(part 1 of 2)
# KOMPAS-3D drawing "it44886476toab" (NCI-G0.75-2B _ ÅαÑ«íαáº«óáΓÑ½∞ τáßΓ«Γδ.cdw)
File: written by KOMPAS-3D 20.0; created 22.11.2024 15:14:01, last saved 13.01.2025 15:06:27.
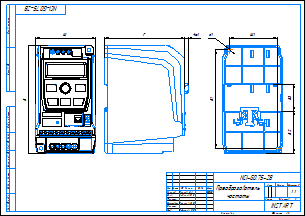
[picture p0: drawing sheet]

Sheet 1: A3, landscape

Document properties: Автор: admin; Полное имя файла: C:\Уралов Работа\Уралов (локальная)\ПЧ\! Китай 3Д-модель NCI\NCI 0.75-2.2 4B\NCI 0.75-2.2 4B.m3d

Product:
- Part/product: it44886476toab
    Масса: 2.32322
  - Body: Тело 17
      Масса: 0.0117014
  - Body: Тело 374
      Масса: 5.48304e-05
  - Body: Тело 265
      Масса: 1.32696e-05
  - Body: Тело 266
      Масса: 1.7366e-05
  - Body: Тело 267
      Масса: 1.7366e-05
  - Body: Тело 103
      Масса: 1.32696e-05
  - Body: Тело 573
      Масса: 4.06595e-05
  - Body: Тело 348
      Масса: 1.32696e-05
  - Body: Тело 270
      Масса: 1.7366e-05
  - Body: Тело 77
      Масса: 1.32696e-05
  - Body: Тело 244
      Масса: 1.65581e-05
  - Body: Тело 536
      Масса: 0.000158536
  - Body: Тело 377
      Масса: 1.65581e-05
  - Body: Тело 272
      Масса: 1.7366e-05
  - Body: Тело 273
      Масса: 5.48304e-05
  - Body: Тело 238
      Масса: 1.7366e-05
  - Body: Тело 274
      Масса: 1.7366e-05
  - Body: Тело 277
      Масса: 1.7366e-05
  - Body: Тело 530
      Масса: 5.61948e-05
  - Body: Тело 278
      Масса: 1.7366e-05
  - Body: Тело 282
      Масса: 1.7366e-05
  - Body: Тело 477
      Масса: 1.51773e-05
  - Body: Тело 526
      Масса: 5.61948e-05
  - Body: Тело 391
      Масса: 1.32696e-05
  - Body: Тело 285
      Масса: 5.48304e-05
  - Body: Тело 287
      Масса: 1.32696e-05
  - Body: Тело 290
      Масса: 0.000413213
  - Body: Тело 269
      Масса: 5.48304e-05
  - Body: Тело 292
      Масса: 1.7366e-05
  - Body: Тело 33
      Масса: 0.00516019
  - Body: Тело 252
      Масса: 5.48304e-05
  - Body: Тело 294
      Масса: 0.000413213
  - Body: Тело 297
      Масса: 3.64631e-05
  - Body: Тело 299
      Масса: 3.64028e-05
  - Body: Тело 283
      Масса: 1.7366e-05
  - Body: Тело 300
      Масса: 1.65581e-05
  - Body: Тело 303
      Масса: 1.65581e-05
  - Body: Тело 516
      Масса: 0.00507377
  - Body: Тело 384
      Масса: 5.48304e-05
  - Body: Тело 360
      Масса: 1.32696e-05
  - Body: Тело 347
      Масса: 1.32696e-05
  - Body: Тело 304
      Масса: 1.65581e-05
  - Body: Тело 307
      Масса: 0.000213463
  - Body: Тело 308
      Масса: 0.000413213
  - Body: Тело 180
      Масса: 1.32696e-05
  - Body: Тело 240
      Масса: 1.7366e-05
  - Body: Тело 309
      Масса: 1.32696e-05
  - Body: Тело 473
      Масса: 0.00425494
  - Body: Тело 311
      Масса: 5.48304e-05
  - Body: Тело 122
      Масса: 1.65581e-05
  - Body: Тело 560
      Масса: 1.65581e-05
  - Body: Тело 312
      Масса: 5.48304e-05
  - Body: Тело 317
      Масса: 1.32696e-05
  - Body: Тело 318
      Масса: 1.32696e-05
  - Body: Тело 321
      Масса: 1.32696e-05
  - Body: Тело 324
      Масса: 1.32696e-05
  - Body: Тело 480
      Масса: 1.51773e-05
  - Body: Тело 288
      Масса: 1.7366e-05
  - Body: Тело 293
      Масса: 5.48304e-05
  - Body: Тело 325
      Масса: 1.32696e-05
  - Body: Тело 99
      Масса: 1.65581e-05
  - Body: Тело 617
      Масса: 1.63919e-05
  - Body: Тело 327
      Масса: 1.32696e-05
  - Body: Тело 31
      Масса: 0.0078835
  - Body: Тело 100
      Масса: 1.65581e-05
  - Body: Тело 105
      Масса: 1.32696e-05
  - Body: Тело 328
      Масса: 1.7366e-05
  - Body: Тело 301
      Масса: 1.65581e-05
  - Body: Тело 331
      Масса: 1.7366e-05
  - Body: Тело 332
      Масса: 1.7366e-05
  - Body: Тело 446
      Масса: 0.000307437
  - Body: Тело 337
      Масса: 1.7366e-05
  - Body: Тело 338
      Масса: 1.7366e-05
  - Body: Тело 570
      Масса: 4.06595e-05
  - Body: Тело 340
      Масса: 1.32696e-05
  - Body: Тело 196
      Масса: 1.32696e-05
  - Body: Тело 357
      Масса: 1.65581e-05
  - Body: Тело 346
      Масса: 1.32696e-05
  - Body: Тело 335
      Масса: 1.32696e-05
  - Body: Тело 281
      Масса: 1.32696e-05
  - Body: Тело 362
      Масса: 1.32696e-05
  - Body: Тело 353
      Масса: 1.7366e-05
  - Body: Тело 355
      Масса: 5.48304e-05
  - Body: Тело 466
      Масса: 0.00829114
  - Body: Тело 358
      Масса: 5.48304e-05
  - Body: Тело 359
      Масса: 1.7366e-05
  - Body: Тело 286
      Масса: 1.7366e-05
  - Body: Тело 86
      Масса: 1.32696e-05
  - Body: Тело 310
      Масса: 1.7366e-05
  - Body: Тело 368
      Масса: 1.32696e-05
  - Body: Тело 370
      Масса: 1.32696e-05
  - Body: Тело 333
      Масса: 1.32696e-05
  - Body: Тело 628
      Масса: 1.51773e-05
  - Body: Тело 371
      Масса: 1.7366e-05
  - Body: Тело 75
      Масса: 1.32696e-05
  - Body: Тело 373
      Масса: 1.32696e-05
  - Body: Тело 375
      Масса: 1.32696e-05
  - Body: Тело 351
      Масса: 2.90876e-05
  - Body: Тело 76
      Масса: 1.65581e-05
  - Body: Тело 259
      Масса: 1.7366e-05
  - Body: Тело 378
      Масса: 0.000413213
  - Body: Тело 95
      Масса: 0.000935996
  - Body: Тело 372
      Масса: 1.7366e-05
  - Body: Тело 322
      Масса: 1.32696e-05
  - Body: Тело 380
      Масса: 1.32696e-05
  - Body: Тело 639
      Масса: 1.63919e-05
  - Body: Тело 385
      Масса: 1.32696e-05
  - Body: Тело 291
      Масса: 0.000213463
  - Body: Тело 386
      Масса: 1.32696e-05
  - Body: Тело 229
      Масса: 1.32696e-05
  - Body: Тело 388
      Масса: 1.32696e-05
  - Body: Тело 389
      Масса: 1.65581e-05
  - Body: Тело 93
      Масса: 3.83377e-05
  - Body: Тело 390
      Масса: 1.65581e-05
  - Body: Тело 143
      Масса: 1.32696e-05
  - Body: Тело 394
      Масса: 1.32696e-05
  - Body: Тело 395
      Масса: 1.32696e-05
  - Body: Тело 354
      Масса: 0.000213463
  - Body: Тело 396
      Масса: 1.7366e-05
  - Body: Тело 397
      Масса: 1.32696e-05
  - Body: Тело 398
      Масса: 1.65581e-05
  - Body: Тело 479
      Масса: 1.51773e-05
  - Body: Тело 402
      Масса: 1.7366e-05
  - Body: Тело 59
      Масса: 1.32696e-05
  - Body: Тело 339
      Масса: 1.32696e-05
  - Body: Тело 404
      Масса: 1.32696e-05
  - Body: Тело 89
      Масса: 0.00142218
  - Body: Тело 406
      Масса: 1.65581e-05
  - Body: Тело 393
      Масса: 1.32696e-05
  - Body: Тело 52
      Масса: 1.32696e-05
  - Body: Тело 407
      Масса: 5.48304e-05
  - Body: Тело 97
      Масса: 0.0015961
  - Body: Тело 410
      Масса: 5.48304e-05
  - Body: Тело 636
      Масса: 1.65581e-05
  - Body: Тело 412
      Масса: 1.7366e-05
  - Body: Тело 413
      Масса: 1.32696e-05
  - Body: Тело 414
      Масса: 1.32696e-05
  - Body: Тело 537
      Масса: 0.000158536
  - Body: Тело 415
      Масса: 1.7366e-05
  - Body: Тело 235
      Масса: 1.7366e-05
  - Body: Тело 419
      Масса: 1.32696e-05
  - Body: Тело 648
      Масса: 0.00426189
  - Body: Тело 420
      Масса: 1.7366e-05
  - Body: Тело 186
      Масса: 1.32696e-05
  - Body: Тело 422
      Масса: 5.48304e-05
  - Body: Тело 381
      Масса: 1.7366e-05
  - Body: Тело 423
      Масса: 1.32696e-05
  - Body: Тело 424
      Масса: 1.7366e-05
  - Body: Тело 98
      Масса: 1.65581e-05
  - Body: Тело 305
      Масса: 1.65581e-05
  - Body: Тело 425
      Масса: 1.32696e-05
  - Body: Тело 365
      Масса: 1.32696e-05
  - Body: Тело 271
      Масса: 1.32696e-05
  - Body: Тело 206
      Масса: 1.32696e-05
  - Body: Тело 429
      Масса: 0.146258
  - Body: Тело 334
      Масса: 1.7366e-05
  - Body: Тело 430
      Масса: 0.146258
  - Body: Тело 350
      Масса: 1.7366e-05
  - Body: Тело 345
      Масса: 1.32696e-05
  - Body: Тело 431
      Масса: 0.146258
  - Body: Тело 364
      Масса: 1.32696e-05
  - Body: Тело 329
      Масса: 1.32696e-05
  - Body: Тело 434
      Масса: 0.000355433
  - Body: Тело 5
      Масса: 0.000355433
  - Body: Тело 124
      Масса: 1.65581e-05
  - Body: Тело 344
      Масса: 1.32696e-05
  - Body: Тело 436
      Масса: 0.000355433
  - Body: Тело 439
      Масса: 0.00113358
  - Body: Тело 606
      Масса: 0.000137594
  - Body: Тело 323
      Масса: 1.32696e-05
  - Body: Тело 441
      Масса: 0.00113358
  - Body: Тело 442
      Масса: 0.000355433
  - Body: Тело 554
      Масса: 4.06595e-05
  - Body: Тело 444
      Масса: 0.000355433
  - Body: Тело 246
      Масса: 1.65581e-05
  - Body: Тело 445
      Масса: 0.00113358
  - Body: Тело 438
      Масса: 0.000355433
  - Body: Тело 106
      Масса: 1.32696e-05
  - Body: Тело 508
      Масса: 1.51773e-05
  - Body: Тело 577
      Масса: 1.7366e-05
  - Body: Тело 392
      Масса: 1.32696e-05
  - Body: Тело 193
      Масса: 1.32696e-05
  - Body: Тело 448
      Масса: 0.000307437
  - Body: Тело 481
      Масса: 1.51773e-05
  - Body: Тело 450
      Масса: 6.34685e-05
  - Body: Тело 222
      Масса: 1.32696e-05
  - Body: Тело 315
      Масса: 1.7366e-05
  - Body: Тело 452
      Масса: 1.63919e-05
  - Body: Тело 53
      Масса: 1.32696e-05
  - Body: Тело 401
      Масса: 1.32696e-05
  - Body: Тело 418
      Масса: 1.7366e-05
  - Body: Тело 517
      Масса: 0.00106884
  - Body: Тело 417
      Масса: 1.32696e-05
  - Body: Тело 453
      Масса: 1.63919e-05
  - Body: Тело 454
      Масса: 0.000382752
  - Body: Тело 428
      Масса: 0.146258
  - Body: Тело 455
      Масса: 1.51773e-05
  - Body: Тело 539
      Масса: 1.51773e-05
  - Body: Тело 457
      Масса: 1.51773e-05
  - Body: Тело 459
      Масса: 3.90329e-05
  - Body: Тело 557
      Масса: 0.00166679
  - Body: Тело 569
      Масса: 1.32696e-05
  - Body: Тело 578
      Масса: 1.32696e-05
  - Body: Тело 626
      Масса: 1.32696e-05
  - Body: Тело 134
      Масса: 1.32696e-05
  - Body: Тело 582
      Масса: 1.65581e-05
  - Body: Тело 203
      Масса: 1.32696e-05
  - Body: Тело 572
      Масса: 1.32696e-05
  - Body: Тело 567
      Масса: 1.32696e-05
  - Body: Тело 207
      Масса: 1.32696e-05
  - Body: Тело 645
      Масса: 1.32696e-05
  - Body: Тело 559
      Масса: 1.65581e-05
  - Body: Тело 152
      Масса: 1.32696e-05
  - Body: Тело 449
      Масса: 0.0658364
  - Body: Тело 316
      Масса: 1.32696e-05
  - Body: Тело 376
      Масса: 1.32696e-05
  - Body: Тело 575
      Масса: 1.32696e-05
  - Body: Тело 576
      Масса: 1.32696e-05
  - Body: Тело 85
      Масса: 1.32696e-05
  - Body: Тело 574
      Масса: 4.06595e-05
  - Body: Тело 399
      Масса: 1.32696e-05
  - Body: Тело 320
      Масса: 1.32696e-05
  - Body: Тело 275
      Масса: 1.7366e-05
  - Body: Тело 213
      Масса: 1.32696e-05
  - Body: Тело 625
      Масса: 1.32696e-05
  - Body: Тело 644
      Масса: 0.000158536
  - Body: Тело 584
      Масса: 4.06595e-05
  - Body: Тело 70
      Масса: 1.65581e-05
  - Body: Тело 588
      Масса: 1.32696e-05
  - Body: Тело 276
      Масса: 1.7366e-05
  - Body: Тело 363
      Масса: 1.32696e-05
  - Body: Тело 474
      Масса: 1.51773e-05
  - Body: Тело 548
      Масса: 2.98222e-05
  - Body: Тело 409
      Масса: 5.48304e-05
  - Body: Тело 472
      Масса: 0.00329327
  - Body: Тело 533
      Масса: 5.61948e-05
  - Body: Тело 647
      Масса: 0.00426189
  - Body: Тело 586
      Масса: 1.32696e-05
  - Body: Тело 262
      Масса: 1.7366e-05
  - Body: Тело 562
      Масса: 0.000382752
  - Body: Тело 379
      Масса: 1.32696e-05
  - Body: Тело 632
      Масса: 1.51773e-05
  - Body: Тело 565
      Масса: 4.06595e-05
  - Body: Тело 118
      Масса: 0.000413213
  - Body: Тело 597
      Масса: 7.12116e-06
  - Body: Тело 613
      Масса: 1.63919e-05
  - Body: Тело 387
      Масса: 1.32696e-05
  - Body: Тело 593
      Масса: 1.32696e-05
  - Body: Тело 408
      Масса: 5.48304e-05
  - Body: Тело 109
      Масса: 1.32696e-05
  - Body: Тело 163
      Масса: 1.32696e-05
  - Body: Тело 488
      Масса: 1.51773e-05
  - Body: Тело 367
      Масса: 1.32696e-05
  - Body: Тело 411
      Масса: 5.48304e-05
  - Body: Тело 583
      Масса: 4.06595e-05
  - Body: Тело 598
      Масса: 7.12116e-06
  - Body: Тело 551
      Масса: 0.000255388
  - Body: Тело 405
      Масса: 1.32696e-05
  - Body: Тело 619
      Масса: 1.32696e-05
  - Body: Тело 361
      Масса: 1.32696e-05
  - Body: Тело 589
      Масса: 1.32696e-05
  - Body: Тело 499
      Масса: 1.51773e-05
  - Body: Тело 440
      Масса: 0.000355433
  - Body: Тело 640
      Масса: 1.63919e-05
  - Body: Тело 150
      Масса: 1.32696e-05
  - Body: Тело 568
      Масса: 1.32696e-05
  - Body: Тело 194
      Масса: 1.32696e-05
  - Body: Тело 251
      Масса: 1.7366e-05
  - Body: Тело 342
      Масса: 0.00166679
  - Body: Тело 604
      Масса: 5.61948e-05
  - Body: Тело 650
      Масса: 0.00426189
  - Body: Тело 161
      Масса: 1.32696e-05
  - Body: Тело 611
      Масса: 0.000158536
  - Body: Тело 210
      Масса: 1.32696e-05
  - Body: Тело 540
      Масса: 1.51773e-05
  - Body: Тело 296
      Масса: 3.6965e-05
  - Body: Тело 601
      Масса: 5.61948e-05
  - Body: Тело 484
      Масса: 0.000158536
  - Body: Тело 622
      Масса: 1.32696e-05
  - Body: Тело 527
      Масса: 0.000141095
  - Body: Тело 624
      Масса: 1.32696e-05
  - Body: Тело 121
      Масса: 0.000413213
  - Body: Тело 600
      Масса: 5.61948e-05
  - Body: Тело 603
      Масса: 5.61948e-05
  - Body: Тело 607
      Масса: 1.32696e-05
  - Body: Тело 289
      Масса: 1.7366e-05
  - Body: Тело 471
      Масса: 0.00329327
  - Body: Тело 313
      Масса: 1.7366e-05
  - Body: Тело 591
      Масса: 7.12116e-06
  - Body: Тело 356
      Масса: 1.65581e-05
  - Body: Тело 306
      Масса: 1.65581e-05
  - Body: Тело 541
      Масса: 0.000158536
  - Body: Тело 511
      Масса: 1.51773e-05
  - Body: Тело 160
      Масса: 1.32696e-05
  - Body: Тело 566
      Масса: 1.32696e-05
  - Body: Тело 563
      Масса: 4.06595e-05
  - Body: Тело 638
      Масса: 1.7366e-05
  - Body: Тело 489
      Масса: 1.51773e-05
  - Body: Тело 456
      Масса: 1.51773e-05
  - Body: Тело 485
      Масса: 0.000158536
  - Body: Тело 284
      Масса: 1.7366e-05
  - Body: Тело 138
      Масса: 2.23009e-05
  - Body: Тело 225
      Масса: 1.32696e-05
  - Body: Тело 546
      Масса: 0.000255388
  - Body: Тело 113
      Масса: 0.000413213
  - Body: Тело 642
      Масса: 3.90329e-05
  - Body: Тело 618
      Масса: 1.63919e-05
  - Body: Тело 525
      Масса: 0.000213463
  - Body: Тело 164
      Масса: 1.32696e-05
  - Body: Тело 253
      Масса: 1.7366e-05
  - Body: Тело 561
      Масса: 1.65581e-05
  - Body: Тело 594
      Масса: 1.32696e-05
  - Body: Тело 482
      Масса: 1.51773e-05
  - Body: Тело 81
      Масса: 1.32696e-05
  - Body: Тело 280
      Масса: 1.32696e-05
  - Body: Тело 494
      Масса: 1.51773e-05
  - Body: Тело 641
      Масса: 3.90329e-05
  - Body: Тело 564
      Масса: 4.06595e-05
  - Body: Тело 633
      Масса: 1.51773e-05
  - Body: Тело 518
      Масса: 0.00166679
  - Body: Тело 620
      Масса: 1.7366e-05
  - Body: Тело 497
      Масса: 1.51773e-05
  - Body: Тело 151
      Масса: 1.65581e-05
  - Body: Тело 302
      Масса: 1.65581e-05
  - Body: Тело 110
      Масса: 1.32696e-05
  - Body: Тело 646
      Масса: 0.000137594
  - Body: Тело 264
      Масса: 1.7366e-05
  - Body: Тело 635
      Масса: 1.65581e-05
  - Body: Тело 608
      Масса: 0.00166679
  - Body: Тело 460
      Масса: 3.90329e-05
  - Body: Тело 403
      Масса: 1.7366e-05
  - Body: Тело 612
      Масса: 0.000158536
  - Body: Тело 492
      Масса: 1.51773e-05
  - Body: Тело 139
      Масса: 0.000194606
  - Body: Тело 400
      Масса: 1.7366e-05
  - Body: Тело 605
      Масса: 5.61948e-05
  - Body: Тело 623
      Масса: 1.32696e-05
  - Body: Тело 117
      Масса: 0.000413213
  - Body: Тело 185
      Масса: 1.32696e-05
  - Body: Тело 631
      Масса: 1.51773e-05
  - Body: Тело 580
      Масса: 1.32696e-05
  - Body: Тело 349
      Масса: 1.7366e-05
  - Body: Тело 621
      Масса: 1.32696e-05
  - Body: Тело 627
      Масса: 0.000255388
  - Body: Тело 531
      Масса: 5.61948e-05
  - Body: Тело 649
      Масса: 0.00426189
  - Body: Тело 585
      Масса: 4.06595e-05
  - Body: Тело 236
      Масса: 1.7366e-05
  - Body: Тело 513
      Масса: 1.51773e-05
  - Body: Тело 426
      Масса: 1.32696e-05
  - Body: Тело 341
      Масса: 0.00166679
  - Body: Тело 470
      Масса: 0.00329329
  - Body: Тело 382
      Масса: 5.48304e-05
  - Body: Тело 227
      Масса: 1.32696e-05
  - Body: Тело 476
      Масса: 1.51773e-05
  - Body: Тело 538
      Масса: 1.51773e-05
  - Body: Тело 596
      Масса: 1.32696e-05
  - Body: Тело 609
      Масса: 1.7366e-05
  - Body: Тело 610
      Масса: 0.00166679
  - Body: Тело 263
      Масса: 1.7366e-05
  - Body: Тело 629
      Масса: 1.51773e-05
  - Body: Тело 336
      Масса: 3.64028e-05
  - Body: Тело 495
      Масса: 1.51773e-05
  - Body: Тело 168
      Масса: 1.32696e-05
  - Body: Тело 298
      Масса: 3.64495e-05
  - Body: Тело 279
      Масса: 1.32696e-05
  - Body: Тело 72
      Масса: 1.65581e-05
  - Body: Тело 500
      Масса: 1.51773e-05
  - Body: Тело 505
      Масса: 1.51773e-05
  - Body: Тело 558
      Масса: 0.00726683
  - Body: Тело 630
      Масса: 1.51773e-05
  - Body: Тело 602
      Масса: 5.61948e-05
  - Body: Тело 556
      Масса: 0.00166679
  - Body: Тело 555
      Масса: 0.00166679
  - Body: Тело 634
      Масса: 1.51773e-05
  - Body: Тело 435
      Масса: 0.00113358
  - Body: Тело 416
      Масса: 1.7366e-05
  - Body: Тело 190
      Масса: 1.32696e-05
  - Body: Тело 330
      Масса: 1.7366e-05
  - Body: Тело 28
      Масса: 0.00135688
  - Body: Тело 553
      Масса: 4.06595e-05
  - Body: Тело 176
      Масса: 1.32696e-05
  - Body: Тело 552
      Масса: 4.06595e-05
  - Body: Тело 534
      Масса: 1.32696e-05
  - Body: Тело 595
      Масса: 1.32696e-05
  - Body: Тело 23
      Масса: 0.0243258
  - Body: Тело 247
      Масса: 1.7366e-05
  - Body: Тело 314
      Масса: 1.7366e-05
  - Body: Тело 126
      Масса: 0.000512664
  - Body: Тело 157
      Масса: 1.32696e-05
  - Body: Тело 550
      Масса: 0.000255388
  - Body: Тело 32
      Масса: 0.0135217
  - Body: Тело 592
      Масса: 7.12116e-06
  - Body: Тело 366
      Масса: 1.7366e-05
  - Body: Тело 504
      Масса: 1.51773e-05
  - Body: Тело 258
      Масса: 1.7366e-05
  - Body: Тело 421
      Масса: 1.7366e-05
  - Body: Тело 35
      Масса: 0.262997
  - Body: Тело 204
      Масса: 1.32696e-05
  - Body: Тело 549
      Масса: 0.000255388
  - Body: Тело 257
      Масса: 1.7366e-05
  - Body: Тело 614
      Масса: 1.63919e-05
  - Body: Тело 547
      Масса: 0.000255388
  - Body: Тело 41
      Масса: 0.0119524
  - Body: Тело 71
      Масса: 1.65581e-05
  - Body: Тело 506
      Масса: 1.51773e-05
  - Body: Тело 545
      Масса: 1.51773e-05
  - Body: Тело 145
      Масса: 1.32696e-05
  - Body: Тело 461
      Масса: 0.000404362
  - Body: Тело 502
      Масса: 1.51773e-05
  - Body: Тело 352
      Масса: 2.90876e-05
  - Body: Тело 120
      Масса: 0.000413213
  - Body: Тело 295
      Масса: 1.65581e-05
  - Body: Тело 544
      Масса: 0.000158536
  - Body: Тело 469
      Масса: 0.0113891
  - Body: Тело 146
      Масса: 1.32696e-05
  - Body: Тело 149
      Масса: 1.32696e-05
  - Body: Тело 615
      Масса: 1.63919e-05
  - Body: Тело 543
      Масса: 0.000158536
  - Body: Тело 542
      Масса: 0.000158536
  - Body: Тело 462
      Масса: 0.000404362
  - Body: Тело 616
      Масса: 1.63919e-05
  - Body: Тело 343
      Масса: 0.00166679
  - Body: Тело 532
      Масса: 5.61948e-05
  - Body: Тело 493
      Масса: 1.51773e-05
  - Body: Тело 529
      Масса: 5.61948e-05
  - Body: Тело 579
      Масса: 0.00017125
  - Body: Тело 200
      Масса: 1.32696e-05
  - Body: Тело 239
      Масса: 5.48304e-05
  - Body: Тело 443
      Масса: 0.00113358
  - Body: Тело 216
      Масса: 0.000280294
  - Body: Тело 468
      Масса: 0.0253857
  - Body: Тело 64
      Масса: 1.65581e-05
  - Body: Тело 528
      Масса: 0.000141095
  - Body: Тело 599
      Масса: 7.12116e-06
  - Body: Тело 590
      Масса: 1.32696e-05
  - Body: Тело 191
      Масса: 1.32696e-05
  - Body: Тело 523
      Масса: 0.000255388
  - Body: Тело 458
      Масса: 1.51773e-05
  - Body: Тело 319
      Масса: 1.32696e-05
  - Body: Тело 49
      Масса: 0.00944
  - Body: Тело 522
      Масса: 1.65581e-05
  - Body: Тело 521
      Масса: 1.32696e-05
  - Body: Тело 571
      Масса: 0.00166679
  - Body: Тело 509
      Масса: 1.51773e-05
  - Body: Тело 326
      Масса: 1.32696e-05
  - Body: Тело 520
      Масса: 5.48304e-05
  - Body: Тело 427
      Масса: 1.32696e-05
  - Body: Тело 519
      Масса: 1.7366e-05
  - Body: Тело 637
      Масса: 1.51773e-05
  - Body: Тело 524
      Масса: 1.65581e-05
  - Body: Тело 432
      Масса: 0.000118347
  - Body: Тело 487
      Масса: 1.65581e-05
  - Body: Тело 510
      Масса: 1.51773e-05
  - Body: Тело 515
      Масса: 0.00507372
  - Body: Тело 512
      Масса: 1.51773e-05
  - Body: Тело 155
      Масса: 1.32696e-05
  - Body: Тело 587
      Масса: 1.32696e-05
  - Body: Тело 174
      Масса: 1.65581e-05
  - Body: Тело 507
      Масса: 1.51773e-05
  - Body: Тело 12
      Масса: 0.000703761
  - Body: Тело 187
      Масса: 1.32696e-05
  - Body: Тело 447
      Масса: 0.000307437
  - Body: Тело 503
      Масса: 1.51773e-05
  - Body: Тело 501
      Масса: 1.51773e-05
  - Body: Тело 369
      Масса: 1.32696e-05
  - Body: Тело 60
      Масса: 1.32696e-05
  - Body: Тело 498
      Масса: 1.51773e-05
  - Body: Тело 535
      Масса: 1.52051e-05
  - Body: Тело 437
      Масса: 0.00113358
  - Body: Тело 496
      Масса: 1.51773e-05
  - Body: Тело 433
      Масса: 0.000118347
  - Body: Тело 491
      Масса: 1.65581e-05
  - Body: Тело 490
      Масса: 1.51773e-05
  - Body: Тело 581
      Масса: 1.65581e-05
  - Body: Тело 486
      Масса: 0.000158536
  - Body: Тело 483
      Масса: 1.51773e-05
  - Body: Тело 514
      Масса: 1.51773e-05
  - Body: Тело 643
      Масса: 0.000158536
  - Body: Тело 125
      Масса: 1.65581e-05
  - Body: Тело 383
      Масса: 0.000340816
  - Body: Тело 465
      Масса: 0.00829114
  - Body: Тело 478
      Масса: 1.51773e-05
  - Body: Тело 451
      Масса: 6.34685e-05
  - Body: Тело 475
      Масса: 1.51773e-05
  - Body: Тело 467
      Масса: 0.00436982
  - Body: Тело 268
      Масса: 5.48304e-05
  - Body: Тело 464
      Масса: 0.00829425
  - Body: Тело 226
      Масса: 0.000413213
  - Body: Тело 463
      Масса: 0.000404362
  - Body: Тело 170
      Масса: 1.32696e-05
  - Body: Тело 261
      Масса: 3.83377e-05
  - Body: Тело 260
      Масса: 1.7366e-05
  - Body: Тело 167
      Масса: 1.32696e-05
  - Body: Тело 256
      Масса: 1.7366e-05
  - Body: Тело 119
      Масса: 0.000413213
  - Body: Тело 255
      Масса: 1.7366e-05
  - Body: Тело 254
      Масса: 1.32696e-05
  - Body: Тело 250
      Масса: 1.7366e-05
  - Body: Тело 249
      Масса: 1.7366e-05
  - Body: Тело 248
      Масса: 1.7366e-05
  - Body: Тело 19
      Масса: 0.0117014
  - Body: Тело 114
      Масса: 0.000413213
  - Body: Тело 234
      Масса: 1.7366e-05
  - Body: Тело 245
      Масса: 1.65581e-05
  - Body: Тело 243
      Масса: 1.65581e-05
  - Body: Тело 242
      Масса: 1.65581e-05
  - Body: Тело 65
      Масса: 1.65581e-05
  - Body: Тело 241
      Масса: 0.000424983
  - Body: Тело 141
      Масса: 0.000213463
  - Body: Тело 237
      Масса: 1.7366e-05
  - Body: Тело 1
      Масса: 0.00113358
  - Body: Тело 233
      Масса: 1.7366e-05
  - Body: Тело 232
      Масса: 5.48304e-05
  - Body: Тело 231
      Масса: 0.00398049
  - Body: Тело 230
      Масса: 1.32696e-05
  - Body: Тело 184
      Масса: 1.32696e-05
  - Body: Тело 228
      Масса: 1.32696e-05
  - Body: Тело 224
      Масса: 1.32696e-05
  - Body: Тело 162
      Масса: 1.65581e-05
  - Body: Тело 223
      Масса: 1.32696e-05
  - Body: Тело 221
      Масса: 1.65581e-05
  - Body: Тело 220
      Масса: 1.32696e-05
  - Body: Тело 219
      Масса: 1.32696e-05
  - Body: Тело 218
      Масса: 1.32696e-05
  - Body: Тело 217
      Масса: 1.32696e-05
  - Body: Тело 215
      Масса: 1.65581e-05
  - Body: Тело 9
      Масса: 0.000703761
  - Body: Тело 214
      Масса: 1.32696e-05
  - Body: Тело 212
      Масса: 1.32696e-05
  - Body: Тело 211
      Масса: 1.32696e-05
  - Body: Тело 209
      Масса: 1.32696e-05
  - Body: Тело 208
      Масса: 1.7366e-05
  - Body: Тело 205
      Масса: 1.32696e-05
  - Body: Тело 202
      Масса: 1.32696e-05
  - Body: Тело 201
      Масса: 1.32696e-05
  - Body: Тело 29
      Масса: 0.00135688
  - Body: Тело 199
      Масса: 1.32696e-05
  - Body: Тело 198
      Масса: 1.32696e-05
  - Body: Тело 197
      Масса: 1.32696e-05
  - Body: Тело 195
      Масса: 1.32696e-05
  - Body: Тело 192
      Масса: 1.32696e-05
  - Body: Тело 189
      Масса: 1.32696e-05
  - Body: Тело 188
      Масса: 1.32696e-05
  - Body: Тело 183
      Масса: 1.32696e-05
  - Body: Тело 182
      Масса: 1.32696e-05
  - Body: Тело 181
      Масса: 1.32696e-05
  - Body: Тело 179
      Масса: 1.32696e-05
  - Body: Тело 178
      Масса: 1.32696e-05
  - Body: Тело 44
      Масса: 0.0119524
  - Body: Тело 50
      Масса: 0.00101975
  - Body: Тело 177
      Масса: 1.32696e-05
  - Body: Тело 175
      Масса: 1.32696e-05
  - Body: Тело 45
      Масса: 0.0267013
  - Body: Тело 137
      Масса: 1.32696e-05
  - Body: Тело 173
      Масса: 1.32696e-05
  - Body: Тело 172
      Масса: 1.65581e-05
  - Body: Тело 153
      Масса: 1.32696e-05
  - Body: Тело 171
      Масса: 1.32696e-05
  - Body: Тело 169
      Масса: 1.32696e-05
  - Body: Тело 140
      Масса: 0.000213463
  - Body: Тело 166
      Масса: 1.32696e-05
  - Body: Тело 165
      Масса: 1.65581e-05
  - Body: Тело 159
      Масса: 1.32696e-05
  - Body: Тело 116
      Масса: 0.000413213
  - Body: Тело 158
      Масса: 1.32696e-05
  - Body: Тело 156
      Масса: 1.32696e-05
  - Body: Тело 154
      Масса: 1.32696e-05
  - Body: Тело 148
      Масса: 1.32696e-05
  - Body: Тело 147
      Масса: 1.32696e-05
  - Body: Тело 24
      Масса: 0.0110484
  - Body: Тело 62
      Масса: 1.32696e-05
  - Body: Тело 144
      Масса: 1.32696e-05
  - Body: Тело 142
      Масса: 0.000213463
  - Body: Тело 136
      Масса: 1.32696e-05
  - Body: Тело 135
      Масса: 1.32696e-05
  - Body: Тело 38
      Масса: 0.00631989
  - Body: Тело 133
      Масса: 1.32696e-05
  - Body: Тело 132
      Масса: 1.32696e-05
  - Body: Тело 131
      Масса: 1.32696e-05
  - Body: Тело 16
      Масса: 0.000703761
  - Body: Тело 130
      Масса: 1.32696e-05
  - Body: Тело 112
      Масса: 0.000413213
  - Body: Тело 129
      Масса: 1.32696e-05
  - Body: Тело 128
      Масса: 1.32696e-05
  - Body: Тело 127
      Масса: 1.32696e-05
  - Body: Тело 123
      Масса: 1.65581e-05
  - Body: Тело 115
      Масса: 0.000413213
  - Body: Тело 111
      Масса: 0.000194606
  - Body: Тело 108
      Масса: 1.32696e-05
  - Body: Тело 107
      Масса: 1.32696e-05
  - Body: Тело 104
      Масса: 1.32696e-05
  - Body: Тело 102
      Масса: 1.32696e-05
  - Body: Тело 90
      Масса: 0.000966482
  - Body: Тело 101
      Масса: 1.32696e-05
  - Body: Тело 96
      Масса: 0.00181049
  - Body: Тело 94
      Масса: 0.00554276
  - Body: Тело 92
      Масса: 3.83377e-05
  - Body: Тело 91
      Масса: 0.0246688
  - Body: Тело 15
      Масса: 0.000703761
  - Body: Тело 88
      Масса: 0.000873873
  - Body: Тело 87
      Масса: 0.000966482
  - Body: Тело 84
      Масса: 1.32696e-05
  - Body: Тело 83
      Масса: 1.32696e-05
  - Body: Тело 82
      Масса: 1.32696e-05
  - Body: Тело 80
      Масса: 1.32696e-05
  - Body: Тело 79
      Масса: 1.32696e-05
  - Body: Тело 78
      Масса: 1.65581e-05
  - Body: Тело 74
      Масса: 1.65581e-05
  - Body: Тело 48
      Масса: 0.00853877
  - Body: Тело 73
      Масса: 1.65581e-05
  - Body: Тело 69
      Масса: 1.65581e-05
  - Body: Тело 68
      Масса: 1.65581e-05
  - Body: Тело 67
      Масса: 1.65581e-05
  - Body: Тело 66
      Масса: 1.65581e-05
  - Body: Тело 63
      Масса: 1.65581e-05
  - Body: Тело 57
      Масса: 1.32696e-05
  - Body: Тело 61
      Масса: 1.32696e-05
  - Body: Тело 58
      Масса: 1.32696e-05
  - Body: Тело 56
      Масса: 1.32696e-05
  - Body: Тело 55
      Масса: 1.32696e-05
  - Body: Тело 54
      Масса: 1.32696e-05
  - Body: Тело 51
      Масса: 1.32696e-05
  - Body: Тело 47
      Масса: 0.551587
  - Body: Тело 46
      Масса: 0.0119034
  - Body: Тело 43
      Масса: 0.0119524
  - Body: Тело 42
      Масса: 0.0119524
  - Body: Тело 40
      Масса: 0.0119524
  - Body: Тело 39
      Масса: 0.0119524
  - Body: Тело 37
      Масса: 0.0343584
  - Body: Тело 36
      Масса: 0.0668131
  - Body: Тело 34
      Масса: 0.00831628
  - Body: Тело 30
      Масса: 0.000935996
  - Body: Тело 27
      Масса: 0.00135688
  - Body: Тело 26
      Масса: 0.00135688
  - Body: Тело 25
      Масса: 0.00135688
  - Body: Тело 22
      Масса: 0.0636504
  - Body: Тело 21
      Масса: 0.0864411
  - Body: Тело 20
      Масса: 0.120334
  - Body: Тело 18
      Масса: 0.0117014
  - Body: Тело 14
      Масса: 0.000703761
  - Body: Тело 13
      Масса: 0.000703761
  - Body: Тело 11
      Масса: 0.000703761
  - Body: Тело 10
      Масса: 0.0160396
  - Body: Тело 8
      Масса: 0.000703761
  - Body: Тело 7
      Масса: 0.000703761
  - Body: Тело 6
      Масса: 0.000355433
  - Body: Тело 4
      Масса: 0.000355433
  - Body: Тело 3
      Масса: 0.00113358
  - Body: Тело 2
      Масса: 0.00113358

Title block, sheet 1: Наименование: Преобразователь / частоты; designation: NCI-G0.75-2B; Количество листов документа: 1; organisation: INSTART; cell 10: Согласовано; Форматы листов документа: A3; stored path: P:\INSTART\Технический отдел\ОР\Прочие задачи\КД на номенклатурный ряд\КД на типоразмеры ПЧ\NCI\NCI-G0.75_P1.5-4B\NCI-G0.75_P1.5-4B _ Преобразователь частоты.cdw; Разработал: Уралов Д.А.; Проверил: Андреев Н.В.; Подписал: Смелков Ж.Е.; Утвердил: Ефремов И.Н.; Разработал, date: 13.01.25

Views: Вид 1
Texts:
  Кривая без истории:10000
  Кривая без истории:10001
  Кривая без истории:10002
  Кривая без истории:10003
  Кривая без истории:10004
  Кривая без истории:10005
  Кривая без истории:10006
  Кривая без истории:10007
  Кривая без истории:10008
  Кривая без истории:10009
  Кривая без истории:10010
  Кривая без истории:10011
  Кривая без истории:10012
  Кривая без истории:10013
  Кривая без истории:10014
  Кривая без истории:10015
  Кривая без истории:10016
  Кривая без истории:10017
  Кривая без истории:10018
  Кривая без истории:10019
  Кривая без истории:10020
  Кривая без истории:10021
  Кривая без истории:10022
  Кривая без истории:10023
  Кривая без истории:10024
  Кривая без истории:10025
  Кривая без истории:10026
  Кривая без истории:10027
  Кривая без истории:10028
  Кривая без истории:10029
  Кривая без истории:10030
  Кривая без истории:10031
  Кривая без истории:10032
  Кривая без истории:10033
  Кривая без истории:10034
  Кривая без истории:10035
  Кривая без истории:10036
  Кривая без истории:10037
  Кривая без истории:10038
  Кривая без истории:10039
  Кривая без истории:10040
  Кривая без истории:10041
  Кривая без истории:10042
  Кривая без истории:10043
  Кривая без истории:10044
  Кривая без истории:10045
  Кривая без истории:10046
  Кривая без истории:10047
  Кривая без истории:10048
  Кривая без истории:10049
  Кривая без истории:10050
  Кривая без истории:10051
  Кривая без истории:10052
  Кривая без истории:10053
  Кривая без истории:10054
  Кривая без истории:10055
  Кривая без истории:10056
  Кривая без истории:10057
  Кривая без истории:10058
  Кривая без истории:10059
  Кривая без истории:10060
  Кривая без истории:10061
  Кривая без истории:10062
  Кривая без истории:10063
  Кривая без истории:10064
  Кривая без истории:10065
  Кривая без истории:10066
  Кривая без истории:10067
  Кривая без истории:10068
  Кривая без истории:10069
  Кривая без истории:10070
  Кривая без истории:10071
  Кривая без истории:10072
  Кривая без истории:10073
  Кривая без истории:10074
  Кривая без истории:10075
  Кривая без истории:10076
  Кривая без истории:10077
  Кривая без истории:10078
  Кривая без истории:10079
  Кривая без истории:10080
  Кривая без истории:10081
  Кривая без истории:10082
  Кривая без истории:10083
  Кривая без истории:10084
  Кривая без истории:10085
  Кривая без истории:10086
  Кривая без истории:10087
  Кривая без истории:10088
  Кривая без истории:10089
  Кривая без истории:10090
  Кривая без истории:10091
  Кривая без истории:10092
  Кривая без истории:10093
  Кривая без истории:10094
  Кривая без истории:10095
  Кривая без истории:10096
  Кривая без истории:10097
  Кривая без истории:10098
  Кривая без истории:10099
  Кривая без истории:10100
  Кривая без истории:10101
  Кривая без истории:10102
  Кривая без истории:10103
  Кривая без истории:10104
  Кривая без истории:10105
  Кривая без истории:10106
  Кривая без истории:10107
  Кривая без истории:10108
  Кривая без истории:10109
  Кривая без истории:10110
  Кривая без истории:10111
  Кривая без истории:10112
  Кривая без истории:10113
  Кривая без истории:10114
  Кривая без истории:10115
  Кривая без истории:10116
  Кривая без истории:10117
  Кривая без истории:10118
  Кривая без истории:10119
  Кривая без истории:10120
  Кривая без истории:10121
  Кривая без истории:10122
  Кривая без истории:10123
  Кривая без истории:10124
  Кривая без истории:10125
  Кривая без истории:10126
  Кривая без истории:10127
  Кривая без истории:10128
  Кривая без истории:10129
  Кривая без истории:10130
  Кривая без истории:10131
  Кривая без истории:10132
  Кривая без истории:10133
  Кривая без истории:10134
  Кривая без истории:10135
  Кривая без истории:10136
  Кривая без истории:10137
  Кривая без истории:10138
  Кривая без истории:10139
  Кривая без истории:10140
  Кривая без истории:10141
  Кривая без истории:10142
  Кривая без истории:10143
  Кривая без истории:10144
  Кривая без истории:10145
  Кривая без истории:10146
  Кривая без истории:10147
  Кривая без истории:10148
  Кривая без истории:10149
  Кривая без истории:10150
  Кривая без истории:10151
  Кривая без истории:10152
  Кривая без истории:10153
  Кривая без истории:10154
  Кривая без истории:10155
  Кривая без истории:10156
  Кривая без истории:10157
  Кривая без истории:10158
  Кривая без истории:10159
  Кривая без истории:10160
  Кривая без истории:10161
  Кривая без истории:10162
  Кривая без истории:10163
  Кривая без истории:10164
  Кривая без истории:10165
  Кривая без истории:10166
  Кривая без истории:10167
  Кривая без истории:10168
  Кривая без истории:10169
  Кривая без истории:10170
  Кривая без истории:10171
  Кривая без истории:10172
  Кривая без истории:10173
  Кривая без истории:10174
  Кривая без истории:10175
  Кривая без истории:10176
  Кривая без истории:10177
  Кривая без истории:10178
  Кривая без истории:10179
  Кривая без истории:10180
  Кривая без истории:10181
  Кривая без истории:10182
  Кривая без истории:10183
  Кривая без истории:10184
  Кривая без истории:10185
  Кривая без истории:10186
  Кривая без истории:10187
  Кривая без истории:10188
  Кривая без истории:10189
  Кривая без истории:10190
  Кривая без истории:10191
  Кривая без истории:10192
  Кривая без истории:10193
  Кривая без истории:10194
  Кривая без истории:10195
  Кривая без истории:10196
  Кривая без истории:10197
  Кривая без истории:10198
  Кривая без истории:10199
  Кривая без истории:10200
  Кривая без истории:10201
  Кривая без истории:10202
  Кривая без истории:10203
  Кривая без истории:10204
  Кривая без истории:10205
  Кривая без истории:10206
  Кривая без истории:10207
  Кривая без истории:10208
  Кривая без истории:10209
  Кривая без истории:10210
  Кривая без истории:10211
  Кривая без истории:10212
  Кривая без истории:10213
  Кривая без истории:10214
  Кривая без истории:10215
  Кривая без истории:10216
  Кривая без истории:10217
  Кривая без истории:10218
  Кривая без истории:10219
  Кривая без истории:10220
  Кривая без истории:10221
  Кривая без истории:10222
  Кривая без истории:10223
  Кривая без истории:10224
  Кривая без истории:10225
  Кривая без истории:10226
  Кривая без истории:10227
  Кривая без истории:10228
  Кривая без истории:10229
  Кривая без истории:10230
  Кривая без истории:10231
  Кривая без истории:10232
  Кривая без истории:10233
  Кривая без истории:10234
  Кривая без истории:10235
  Кривая без истории:10236
  Кривая без истории:10237
  Кривая без истории:10238
  Кривая без истории:10239
  Кривая без истории:10240
  Кривая без истории:10241
  Кривая без истории:10242
  Кривая без истории:10243
  Кривая без истории:10244
  Кривая без истории:10245
  Кривая без истории:10246
  Кривая без истории:10247
  Кривая без истории:10248
  Кривая без истории:10249
  Кривая без истории:10250
  Кривая без истории:10251
  Кривая без истории:10252
  Кривая без истории:10253
  Кривая без истории:10254
  Кривая без истории:10255
  Кривая без истории:10256
  Кривая без истории:10257
  Кривая без истории:10258
  Кривая без истории:10259
  Кривая без истории:10260
  Кривая без истории:10261
  Кривая без истории:10262
  Кривая без истории:10263
  Кривая без истории:10264
  Кривая без истории:10265
  Кривая без истории:10266
  Кривая без истории:10267
  Кривая без истории:10268
  Кривая без истории:10269
  Кривая без истории:10270
  Кривая без истории:10271
  Кривая без истории:10272
  Кривая без истории:10273
  Кривая без истории:10274
  Кривая без истории:10275
  Кривая без истории:10276
  Кривая без истории:10277
  Кривая без истории:10278
  Кривая без истории:10279
  Кривая без истории:10280
  Кривая без истории:10281
  Кривая без истории:10282
  Кривая без истории:10283
  Кривая без истории:10284
  Кривая без истории:10285
  Кривая без истории:10286
  Кривая без истории:10287
  Кривая без истории:10288
  Кривая без истории:10289
  Кривая без истории:10290
  Кривая без истории:10291
  Кривая без истории:10292
  Кривая без истории:10293
  Кривая без истории:10294
  Кривая без истории:10295
  Кривая без истории:10296
  Кривая без истории:10297
  Кривая без истории:10298
  Кривая без истории:10299
  Кривая без истории:10300
  Кривая без истории:10301
  Кривая без истории:10302
  Кривая без истории:10303
  Кривая без истории:10304
  Кривая без истории:10305
  Кривая без истории:10306
  Кривая без истории:10307
  Кривая без истории:10308
  Кривая без истории:10309
  Кривая без истории:10310
  Кривая без истории:10311
  Кривая без истории:10312
  Кривая без истории:10313
  Кривая без истории:10314
  Кривая без истории:10315
  Кривая без истории:10316
  Кривая без истории:10317
  Кривая без истории:10318
  Кривая без истории:10319
  Кривая без истории:10320
  Кривая без истории:10321
  Кривая без истории:10322
  Кривая без истории:10323
  Кривая без истории:10324
  Кривая без истории:10325
  Кривая без истории:10326
  Кривая без истории:10327
  Кривая без истории:10328
  Кривая без истории:10329
  Кривая без истории:10330
  Кривая без истории:10331
  Кривая без истории:10332
  Кривая без истории:10333
  Кривая без истории:10334
  Кривая без истории:10335
  Кривая без истории:10336
  Кривая без истории:10337
  Кривая без истории:10338
  Кривая без истории:10339
  Кривая без истории:10340
  Кривая без истории:10341
  Кривая без истории:10342
  Кривая без истории:10343
  Кривая без истории:10344
  Кривая без истории:10345
  Кривая без истории:10346
  Кривая без истории:10347
  Кривая без истории:10348
  Кривая без истории:10349
  Кривая без истории:10350
  Кривая без истории:10351
  Кривая без истории:10352
  Кривая без истории:10353
  Кривая без истории:10354
  Кривая без истории:10355
  Кривая без истории:10356
  Кривая без истории:10357
  Кривая без истории:10358
  Кривая без истории:10359
  Кривая без истории:10360
  Кривая без истории:10361
  Кривая без истории:10362
  Кривая без истории:10363
  Кривая без истории:10364
  Кривая без истории:10365
  Кривая без истории:10366
  Кривая без истории:10367
  Кривая без истории:10368
  Кривая без истории:10369
  Кривая без истории:10370
  Кривая без истории:10371
  Кривая без истории:10372
  Кривая без истории:10373
  Кривая без истории:10374
  Кривая без истории:10375
  Кривая без истории:10376
  Кривая без истории:10377
  Кривая без истории:10378
  Кривая без истории:10379
  Кривая без истории:10380
  Кривая без истории:10381
  Кривая без истории:10382
  Кривая без истории:10383
  Кривая без истории:10384
  Кривая без истории:10385
  Кривая без истории:10386
  Кривая без истории:10387
  Кривая без истории:10388
  Кривая без истории:10389
  Кривая без истории:10390
  Кривая без истории:10391
  Кривая без истории:10392
  Кривая без истории:10393
  Кривая без истории:10394
  Кривая без истории:10395
  Кривая без истории:10396
  Кривая без истории:10397
  Кривая без истории:10398
  Кривая без истории:10399
  Кривая без истории:10400
  Кривая без истории:10401
  Кривая без истории:10402
  Кривая без истории:10403
  Кривая без истории:10404
  Кривая без истории:10405
  Кривая без истории:10406
  Кривая без истории:10407
  Кривая без истории:10408
  Кривая без истории:10409
  Кривая без истории:10410
  Кривая без истории:10411
  Кривая без истории:10412
  Кривая без истории:10413
  Кривая без истории:10414
  Кривая без истории:10415
  Кривая без истории:10416
  Кривая без истории:10417
  Кривая без истории:10418
  Кривая без истории:10419
  Кривая без истории:10420
  Кривая без истории:10421
  Кривая без истории:10422
  Кривая без истории:10423
  Кривая без истории:10424
  Кривая без истории:10425
  Кривая без истории:10426
  Кривая без истории:10427
  Кривая без истории:10428
  Кривая без истории:10429
  Кривая без истории:10430
  Кривая без истории:10431
  Кривая без истории:10432
  Кривая без истории:10433
  Кривая без истории:10434
  Кривая без истории:10435
  Кривая без истории:10436
  Кривая без истории:10437
  Кривая без истории:10438
  Кривая без истории:10439
  Кривая без истории:10440
  Кривая без истории:10441
  Кривая без истории:10442
  Кривая без истории:10443
  Кривая без истории:10444
  Кривая без истории:10445
  Кривая без истории:10446
  Кривая без истории:10447
  Кривая без истории:10448
  Кривая без истории:10449
  Кривая без истории:10450
  Кривая без истории:10451
  Кривая без истории:10452
  Кривая без истории:10453
  Кривая без истории:10454
  Кривая без истории:10455
  Кривая без истории:10456
  Кривая без истории:10457
  Кривая без истории:10458
  Кривая без истории:10459
  Кривая без истории:10460
  Кривая без истории:10461
  Кривая без истории:10462
  Кривая без истории:10463
  Кривая без истории:10464
  Кривая без истории:10465
  Кривая без истории:10466
  Кривая без истории:10467
  Кривая без истории:10468
  Кривая без истории:10469
  Кривая без истории:10470
  Кривая без истории:10471
  Кривая без истории:10472
  Кривая без истории:10473
  Кривая без истории:10474
  Кривая без истории:10475
  Кривая без истории:10476
  Кривая без истории:10477
  Кривая без истории:10478
  Кривая без истории:10479
  Кривая без истории:10480
  Кривая без истории:10481
  Кривая без истории:10482
  Кривая без истории:10483
  Кривая без истории:10484
  Кривая без истории:10485
  Кривая без истории:10486
  Кривая без истории:10487
  Кривая без истории:10488
  Кривая без истории:10489
  Кривая без истории:10490
  Кривая без истории:10491
  Кривая без истории:10492
  Кривая без истории:10493
  Кривая без истории:10494
  Кривая без истории:10495
  Кривая без истории:10496
  Кривая без истории:10497
  Кривая без истории:10498
  Кривая без истории:10499
  Кривая без истории:10500
  Кривая без истории:10501
  Кривая без истории:10502
  Кривая без истории:10503
  Кривая без истории:10504
  Кривая без истории:10505
  Кривая без истории:10506
  Кривая без истории:10507
  Кривая без истории:10508
  Кривая без истории:10509
  Кривая без истории:10510
  Кривая без истории:10511
  Кривая без истории:10512
  Кривая без истории:10513
  Кривая без истории:10514
  Кривая без истории:10515
  Кривая без истории:10516
  Кривая без истории:10517
  Кривая без истории:10518
  Кривая без истории:10519
  Кривая без истории:10520
  Кривая без истории:10521
  Кривая без истории:10522
  Кривая без истории:10523
  Кривая без истории:10524
  Кривая без истории:10525
  Кривая без истории:10526
  Кривая без истории:10527
  Кривая без истории:10528
  Кривая без истории:10529
  Кривая без истории:10530
  Кривая без истории:10531
  Кривая без истории:10532
  Кривая без истории:10533
  Кривая без истории:10534
  Кривая без истории:10535
  Кривая без истории:10536
  Кривая без истории:10537
  Кривая без истории:10538
  Кривая без истории:10539
  Кривая без истории:10540
  Кривая без истории:10541
  Кривая без истории:10542
  Кривая без истории:10543
  Кривая без истории:10544
  Кривая без истории:10545
  Кривая без истории:10546
  Кривая без истории:10547
  Кривая без истории:10548
  Кривая без истории:10549
  Кривая без истории:10550
  Кривая без истории:10551
  Кривая без истории:10552
  Кривая без истории:10553
  Кривая без истории:10554
  Кривая без истории:10555
  Кривая без истории:10556
  Кривая без истории:10557
  Кривая без истории:10558
  Кривая без истории:10559
  Кривая без истории:10560
  Кривая без истории:10561
  Кривая без истории:10562
  Кривая без истории:10563
  Кривая без истории:10564
  Кривая без истории:10565
  Кривая без истории:10566
  Кривая без истории:10567
  Кривая без истории:10568
  Кривая без истории:10569
  Кривая без истории:10570
  Кривая без истории:10571
  Кривая без истории:10572
  Кривая без истории:10573
  Кривая без истории:10574
  Кривая без истории:10575
  Кривая без истории:10576
  Кривая без истории:10577
  Кривая без истории:10578
  Кривая без истории:10579
  Кривая без истории:10580
  Кривая без истории:10581
  Кривая без истории:10582
  Кривая без истории:10583
  Кривая без истории:10584
  Кривая без истории:10585
  Кривая без истории:10586
  Кривая без истории:10587
  Кривая без истории:10588
  Кривая без истории:10589
  Кривая без истории:10590
  Кривая без истории:10591
  Кривая без истории:10592
  Кривая без истории:10593
  Кривая без истории:10594
  Кривая без истории:10595
  Кривая без истории:10596
  Кривая без истории:10597
  Кривая без истории:10598
  Кривая без истории:10599
  Кривая без истории:10600
  Кривая без истории:10601
  Кривая без истории:10602
  Кривая без истории:10603
  Кривая без истории:10604
  Кривая без истории:10605
  Кривая без истории:10606
  Кривая без истории:10607
  Кривая без истории:10608
  Кривая без истории:10609
  Кривая без истории:10610
  Кривая без истории:10611
  Кривая без истории:10612
  Кривая без истории:10613
  Кривая без истории:10614
  Кривая без истории:10615
  Кривая без истории:10616
  Кривая без истории:10617
  Кривая без истории:10618
  Кривая без истории:10619
  Кривая без истории:10620
  Кривая без истории:10621
  Кривая без истории:10622
  Кривая без истории:10623
  Кривая без истории:10624
  Кривая без истории:10625
  Кривая без истории:10626
  Кривая без истории:10627
  Кривая без истории:10628
  Кривая без истории:10629
  Кривая без истории:10630
  Кривая без истории:10631
  Кривая без истории:10632
  Кривая без истории:10633
  Кривая без истории:10634
  Кривая без истории:10635
  Кривая без истории:10636
  Кривая без истории:10637
  Кривая без истории:10638
  Кривая без истории:10639
  Кривая без истории:10640
  Кривая без истории:10641
  Кривая без истории:10642
  Кривая без истории:10643
  Кривая без истории:10644
  Кривая без истории:10645
  Кривая без истории:10646
  Кривая без истории:10647
  Кривая без истории:10648
  Кривая без истории:10649
  Кривая без истории:10650
  Кривая без истории:10651
  Кривая без истории:10652
  Кривая без истории:10653
  Кривая без истории:10654
  Кривая без истории:10655
  Кривая без истории:10656
  Кривая без истории:10657
  Кривая без истории:10658
  Кривая без истории:10659
  Кривая без истории:10660
  Кривая без истории:10661
  Кривая без истории:10662
  Кривая без истории:10663
  Кривая без истории:10664
  Кривая без истории:10665
  Кривая без истории:10666
  Кривая без истории:10667
  Кривая без истории:10668
  Кривая без истории:10669
  Кривая без истории:10670
  Кривая без истории:10671
  Кривая без истории:10672
  Кривая без истории:10673
  Кривая без истории:10674
  Кривая без истории:10675
  Кривая без истории:10676
  Кривая без истории:10677
  Кривая без истории:10678
  Кривая без истории:10679
  Кривая без истории:10680
  Кривая без истории:10681
  Кривая без истории:10682
  Кривая без истории:10683
  Кривая без истории:10684
  Кривая без истории:10685
  Кривая без истории:10686
  Кривая без истории:10687
  Кривая без истории:10688
  Кривая без истории:10689
  Кривая без истории:10690
  Кривая без истории:10691
  Кривая без истории:10692
  Кривая без истории:10693
  Кривая без истории:10694
  Кривая без истории:10695
  Кривая без истории:10696
  Кривая без истории:10697
  Кривая без истории:10698
  Кривая без истории:10699
  Кривая без истории:10700
  Кривая без истории:10701
  Кривая без истории:10702
  Кривая без истории:10703
  Кривая без истории:10704
  Кривая без истории:10705
  Кривая без истории:10706
  Кривая без истории:10707
  Кривая без истории:10708
  Кривая без истории:10709
  Кривая без истории:10710
  Кривая без истории:10711
  Кривая без истории:10712
  Кривая без истории:10713
  Кривая без истории:10714
  Кривая без истории:10715
  Кривая без истории:10716
  Кривая без истории:10717
  Кривая без истории:10718
  Кривая без истории:10719
  Кривая без истории:10720
  Кривая без истории:10721
  Кривая без истории:10722
  Кривая без истории:10723
  Кривая без истории:10724
  Кривая без истории:10725
  Кривая без истории:10726
  Кривая без истории:10727
  Кривая без истории:10728
  Кривая без истории:10729
  Кривая без истории:10730
  Кривая без истории:10731
  Кривая без истории:10732
  Кривая без истории:10733
  Кривая без истории:10734
  Кривая без истории:10735
  Кривая без истории:10736
  Кривая без истории:10737
  Кривая без истории:10738
  Кривая без истории:10739
  Кривая без истории:10740
  Кривая без истории:10741
  Кривая без истории:10742
  Кривая без истории:10743
  Кривая без истории:10744
  Кривая без истории:10745
  Кривая без истории:10746
  Кривая без истории:10747
  Кривая без истории:10748
  Кривая без истории:10749
  Кривая без истории:10750
  Кривая без истории:10751
  Кривая без истории:10752
  Кривая без истории:10753
  Кривая без истории:10754
  Кривая без истории:10755
  Кривая без истории:10756
  Кривая без истории:10757
  Кривая без истории:10758
  Кривая без истории:10759
  Кривая без истории:10760
  Кривая без истории:10761
  Кривая без истории:10762
  Кривая без истории:10763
